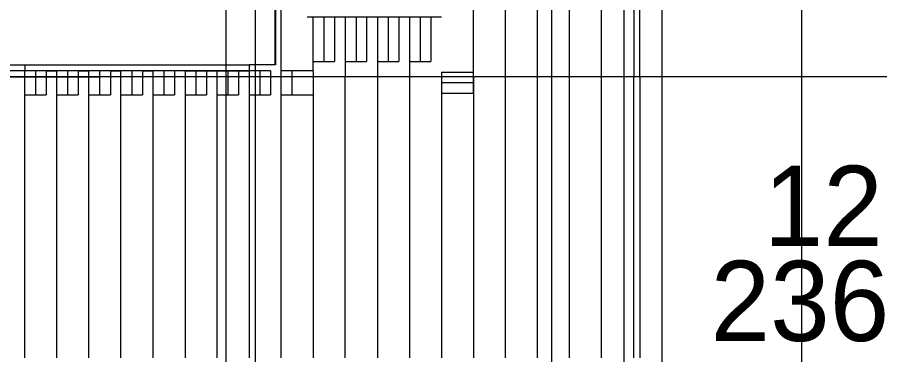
# Model space of a CAD drawing. Extents: x -264165 to -263575, y -1242333 to -1242036.
# Drawn here: x -263907.56 to -263886.03, y -1242216.81 to -1242208.39 of the extents above; entities that cross this region are included whole.
import ezdxf

# ---------------------------------------------------------------- set-up
doc = ezdxf.new("R2010")
doc.units = 0
for name, color, linetype in [('KFA_BODY_VYTYCOVAK', 7, 'Continuous'), ('KFA_HESCON_OSI_STAVBY', 7, 'Continuous'), ('KFA_SITUACIA_DRS_VYTYCOVAK_SEDA', 7, 'Continuous')]:
    doc.layers.add(name, color=color, linetype=linetype)

msp = doc.modelspace()

# ---------------------------------------------------------------- linework, layer by layer
at = {"layer": 'KFA_HESCON_OSI_STAVBY'}
for p, q in [((-263901.618, -1242080.447), (-263901.618, -1242248.737)), ((-263894.218, -1242080.447), (-263894.218, -1242248.737)), ((-263892.418, -1242080.447), (-263892.418, -1242248.737)), ((-263891.468, -1242080.447), (-263891.468, -1242248.737)), ((-263787.486, -1242209.882), (-263921.823, -1242209.882)), ((-263920.885, -1242209.882), (-263905.505, -1242209.882))]:
    msp.add_line(p, q, dxfattribs=at)
at = {"layer": 'KFA_SITUACIA_DRS_VYTYCOVAK_SEDA'}
for p, q in [((-263887.968, -1242220.382), (-263887.968, -1242108.382)), ((-263901.118, -1242209.582), (-263901.118, -1242203.032)), ((-263901.118, -1242209.582), (-263901.118, -1242203.032)), ((-263901.108, -1242203.032), (-263901.108, -1242209.582)), ((-263901.108, -1242203.032), (-263901.108, -1242209.582)), ((-263900.968, -1242209.582), (-263900.968, -1242203.032)), ((-263900.968, -1242209.582), (-263900.968, -1242203.032)), ((-263896.168, -1242209.882), (-263896.168, -1242202.882)), ((-263896.168, -1242209.882), (-263896.168, -1242202.882)), ((-263895.368, -1242209.882), (-263895.368, -1242202.882)), ((-263895.368, -1242209.882), (-263895.368, -1242202.882)), ((-263894.568, -1242209.882), (-263894.568, -1242202.882)), ((-263894.568, -1242209.882), (-263894.568, -1242202.882)), ((-263893.768, -1242209.882), (-263893.768, -1242202.882)), ((-263893.768, -1242209.882), (-263893.768, -1242202.882)), ((-263892.968, -1242209.882), (-263892.968, -1242202.882)), ((-263892.968, -1242209.882), (-263892.968, -1242202.882)), ((-263902.343, -1242224.282), (-263902.343, -1242203.332)), ((-263896.168, -1242209.761), (-263896.168, -1242206.932)), ((-263896.168, -1242209.761), (-263896.168, -1242206.932)), ((-263892.168, -1242207.032), (-263892.168, -1242209.882)), ((-263892.168, -1242207.032), (-263892.168, -1242209.882)), ((-263892.018, -1242209.882), (-263892.018, -1242207.032)), ((-263892.018, -1242209.882), (-263892.018, -1242207.032)), ((-263900.168, -1242208.395), (-263900.318, -1242208.395)), ((-263900.168, -1242208.395), (-263900.318, -1242208.395)), ((-263899.901, -1242208.395), (-263900.168, -1242208.395)), ((-263899.901, -1242208.395), (-263900.168, -1242208.395)), ((-263900.168, -1242209.732), (-263900.168, -1242208.395)), ((-263900.168, -1242209.732), (-263900.168, -1242208.395)), ((-263899.901, -1242208.395), (-263899.901, -1242209.495)), ((-263899.901, -1242208.395), (-263899.901, -1242209.495)), ((-263899.634, -1242208.395), (-263899.901, -1242208.395)), ((-263899.634, -1242208.395), (-263899.901, -1242208.395)), ((-263899.634, -1242208.395), (-263899.634, -1242209.495)), ((-263899.634, -1242208.395), (-263899.634, -1242209.495)), ((-263899.368, -1242208.395), (-263899.634, -1242208.395)), ((-263899.368, -1242208.395), (-263899.634, -1242208.395)), ((-263899.101, -1242208.395), (-263899.368, -1242208.395)), ((-263899.101, -1242208.395), (-263899.368, -1242208.395)), ((-263899.368, -1242208.395), (-263899.368, -1242209.882)), ((-263899.368, -1242208.395), (-263899.368, -1242209.882)), ((-263899.101, -1242208.395), (-263899.101, -1242209.495)), ((-263899.101, -1242208.395), (-263899.101, -1242209.495)), ((-263898.835, -1242208.395), (-263899.101, -1242208.395)), ((-263898.835, -1242208.395), (-263899.101, -1242208.395)), ((-263898.835, -1242208.395), (-263898.835, -1242209.495)), ((-263898.835, -1242208.395), (-263898.835, -1242209.495)), ((-263898.568, -1242208.395), (-263898.835, -1242208.395)), ((-263898.568, -1242208.395), (-263898.835, -1242208.395)), ((-263898.301, -1242208.395), (-263898.568, -1242208.395)), ((-263898.301, -1242208.395), (-263898.568, -1242208.395)), ((-263898.568, -1242208.395), (-263898.568, -1242209.882)), ((-263898.568, -1242208.395), (-263898.568, -1242209.882)), ((-263898.301, -1242208.395), (-263898.301, -1242209.495)), ((-263898.301, -1242208.395), (-263898.301, -1242209.495)), ((-263898.034, -1242208.395), (-263898.301, -1242208.395)), ((-263898.034, -1242208.395), (-263898.301, -1242208.395)), ((-263898.034, -1242208.395), (-263898.034, -1242209.495)), ((-263898.034, -1242208.395), (-263898.034, -1242209.495)), ((-263897.768, -1242208.395), (-263898.034, -1242208.395)), ((-263897.768, -1242208.395), (-263898.034, -1242208.395)), ((-263897.501, -1242208.395), (-263897.768, -1242208.395)), ((-263897.501, -1242208.395), (-263897.768, -1242208.395)), ((-263897.768, -1242208.395), (-263897.768, -1242209.882)), ((-263897.768, -1242208.395), (-263897.768, -1242209.882)), ((-263897.234, -1242208.395), (-263897.501, -1242208.395)), ((-263897.234, -1242208.395), (-263897.501, -1242208.395)), ((-263897.501, -1242208.395), (-263897.501, -1242209.495)), ((-263897.501, -1242208.395), (-263897.501, -1242209.495)), ((-263897.234, -1242208.395), (-263897.234, -1242209.495)), ((-263897.234, -1242208.395), (-263897.234, -1242209.495)), ((-263896.968, -1242208.395), (-263897.234, -1242208.395)), ((-263896.968, -1242208.395), (-263897.234, -1242208.395)), ((-263900.168, -1242209.495), (-263899.901, -1242209.495)), ((-263900.168, -1242209.495), (-263899.901, -1242209.495)), ((-263899.901, -1242209.495), (-263899.634, -1242209.495)), ((-263899.901, -1242209.495), (-263899.634, -1242209.495)), ((-263899.368, -1242209.495), (-263899.101, -1242209.495)), ((-263899.368, -1242209.495), (-263899.101, -1242209.495)), ((-263899.101, -1242209.495), (-263898.835, -1242209.495)), ((-263899.101, -1242209.495), (-263898.835, -1242209.495)), ((-263898.568, -1242209.495), (-263898.301, -1242209.495)), ((-263898.568, -1242209.495), (-263898.301, -1242209.495)), ((-263898.301, -1242209.495), (-263898.034, -1242209.495)), ((-263898.301, -1242209.495), (-263898.034, -1242209.495)), ((-263897.768, -1242209.495), (-263897.501, -1242209.495)), ((-263897.768, -1242209.495), (-263897.501, -1242209.495)), ((-263897.501, -1242209.495), (-263897.234, -1242209.495)), ((-263897.501, -1242209.495), (-263897.234, -1242209.495)), ((-263907.893, -1242209.582), (-263907.368, -1242209.582)), ((-263907.893, -1242209.582), (-263907.368, -1242209.582)), ((-263907.368, -1242209.582), (-263907.368, -1242209.732)), ((-263907.368, -1242209.582), (-263907.368, -1242209.732)), ((-263907.368, -1242209.582), (-263901.768, -1242209.582)), ((-263907.368, -1242209.582), (-263901.768, -1242209.582)), ((-263901.108, -1242209.582), (-263901.768, -1242209.582)), ((-263901.108, -1242209.582), (-263901.768, -1242209.582)), ((-263901.768, -1242209.582), (-263901.768, -1242209.732)), ((-263901.768, -1242209.582), (-263901.768, -1242209.732)), ((-263901.768, -1242209.582), (-263901.768, -1242209.732)), ((-263901.768, -1242209.582), (-263901.768, -1242209.732)), ((-263900.968, -1242216.882), (-263900.968, -1242209.582)), ((-263900.968, -1242216.882), (-263900.968, -1242209.582)), ((-263907.368, -1242209.732), (-263907.893, -1242209.732)), ((-263907.368, -1242209.732), (-263907.893, -1242209.732)), ((-263907.368, -1242209.732), (-263907.893, -1242209.732)), ((-263907.368, -1242209.732), (-263907.893, -1242209.732)), ((-263907.101, -1242209.732), (-263907.368, -1242209.732)), ((-263907.101, -1242209.732), (-263907.368, -1242209.732)), ((-263907.368, -1242216.882), (-263907.368, -1242209.732)), ((-263907.368, -1242216.882), (-263907.368, -1242209.732)), ((-263901.768, -1242209.732), (-263907.368, -1242209.732)), ((-263901.768, -1242209.732), (-263907.368, -1242209.732)), ((-263907.101, -1242209.732), (-263907.101, -1242210.332)), ((-263907.101, -1242209.732), (-263907.101, -1242210.332)), ((-263906.834, -1242209.732), (-263907.101, -1242209.732)), ((-263906.834, -1242209.732), (-263907.101, -1242209.732)), ((-263906.834, -1242209.732), (-263906.834, -1242210.332)), ((-263906.834, -1242209.732), (-263906.834, -1242210.332)), ((-263906.834, -1242209.732), (-263906.568, -1242209.732)), ((-263906.834, -1242209.732), (-263906.568, -1242209.732)), ((-263906.301, -1242209.732), (-263906.568, -1242209.732)), ((-263906.301, -1242209.732), (-263906.568, -1242209.732)), ((-263906.568, -1242216.882), (-263906.568, -1242209.732)), ((-263906.568, -1242216.882), (-263906.568, -1242209.732)), ((-263906.301, -1242209.732), (-263906.301, -1242210.332)), ((-263906.301, -1242209.732), (-263906.301, -1242210.332)), ((-263906.034, -1242209.732), (-263906.301, -1242209.732)), ((-263906.034, -1242209.732), (-263906.301, -1242209.732)), ((-263906.034, -1242209.732), (-263906.034, -1242210.332)), ((-263906.034, -1242209.732), (-263906.034, -1242210.332)), ((-263906.034, -1242209.732), (-263905.768, -1242209.732)), ((-263906.034, -1242209.732), (-263905.768, -1242209.732)), ((-263905.768, -1242209.732), (-263905.908, -1242209.732)), ((-263905.768, -1242209.732), (-263905.908, -1242209.732)), ((-263905.501, -1242209.732), (-263905.768, -1242209.732)), ((-263905.501, -1242209.732), (-263905.768, -1242209.732)), ((-263905.768, -1242216.882), (-263905.768, -1242209.732)), ((-263905.768, -1242216.882), (-263905.768, -1242209.732)), ((-263905.501, -1242209.732), (-263905.501, -1242210.332)), ((-263905.501, -1242209.732), (-263905.501, -1242210.332)), ((-263905.234, -1242209.732), (-263905.501, -1242209.732)), ((-263905.234, -1242209.732), (-263905.501, -1242209.732)), ((-263905.234, -1242209.732), (-263905.234, -1242210.332)), ((-263905.234, -1242209.732), (-263905.234, -1242210.332)), ((-263905.234, -1242209.732), (-263904.968, -1242209.732)), ((-263905.234, -1242209.732), (-263904.968, -1242209.732)), ((-263904.968, -1242209.732), (-263905.108, -1242209.732)), ((-263904.968, -1242209.732), (-263905.108, -1242209.732)), ((-263904.701, -1242209.732), (-263904.968, -1242209.732)), ((-263904.701, -1242209.732), (-263904.968, -1242209.732)), ((-263904.968, -1242216.882), (-263904.968, -1242209.732)), ((-263904.968, -1242216.882), (-263904.968, -1242209.732)), ((-263904.701, -1242209.732), (-263904.701, -1242210.332)), ((-263904.701, -1242209.732), (-263904.701, -1242210.332)), ((-263904.434, -1242209.732), (-263904.701, -1242209.732)), ((-263904.434, -1242209.732), (-263904.701, -1242209.732)), ((-263904.434, -1242209.732), (-263904.434, -1242210.332)), ((-263904.434, -1242209.732), (-263904.434, -1242210.332)), ((-263904.434, -1242209.732), (-263904.168, -1242209.732)), ((-263904.434, -1242209.732), (-263904.168, -1242209.732)), ((-263904.168, -1242209.732), (-263904.308, -1242209.732)), ((-263904.168, -1242209.732), (-263904.308, -1242209.732)), ((-263903.901, -1242209.732), (-263904.168, -1242209.732)), ((-263903.901, -1242209.732), (-263904.168, -1242209.732)), ((-263903.368, -1242209.732), (-263904.168, -1242209.732)), ((-263903.368, -1242209.732), (-263904.168, -1242209.732)), ((-263904.168, -1242216.882), (-263904.168, -1242209.732)), ((-263904.168, -1242216.882), (-263904.168, -1242209.732)), ((-263903.901, -1242209.732), (-263903.901, -1242210.332)), ((-263903.901, -1242209.732), (-263903.901, -1242210.332)), ((-263903.634, -1242209.732), (-263903.901, -1242209.732)), ((-263903.634, -1242209.732), (-263903.901, -1242209.732)), ((-263903.634, -1242209.732), (-263903.634, -1242210.332)), ((-263903.634, -1242209.732), (-263903.634, -1242210.332)), ((-263903.101, -1242209.732), (-263903.368, -1242209.732)), ((-263903.101, -1242209.732), (-263903.368, -1242209.732)), ((-263903.368, -1242209.732), (-263902.568, -1242209.732)), ((-263903.368, -1242209.732), (-263902.568, -1242209.732)), ((-263903.368, -1242209.732), (-263903.368, -1242216.882)), ((-263903.368, -1242209.732), (-263903.368, -1242216.882)), ((-263903.101, -1242209.732), (-263903.101, -1242210.332)), ((-263903.101, -1242209.732), (-263903.101, -1242210.332)), ((-263902.834, -1242209.732), (-263903.101, -1242209.732)), ((-263902.834, -1242209.732), (-263903.101, -1242209.732)), ((-263902.834, -1242209.732), (-263902.834, -1242210.332)), ((-263902.834, -1242209.732), (-263902.834, -1242210.332)), ((-263902.301, -1242209.732), (-263902.568, -1242209.732)), ((-263902.301, -1242209.732), (-263902.568, -1242209.732)), ((-263902.568, -1242209.732), (-263901.768, -1242209.732)), ((-263902.568, -1242209.732), (-263901.768, -1242209.732)), ((-263902.568, -1242216.882), (-263902.568, -1242209.732)), ((-263902.568, -1242216.882), (-263902.568, -1242209.732)), ((-263902.301, -1242209.732), (-263902.301, -1242210.332)), ((-263902.301, -1242209.732), (-263902.301, -1242210.332)), ((-263902.034, -1242209.732), (-263902.301, -1242209.732)), ((-263902.034, -1242209.732), (-263902.301, -1242209.732)), ((-263902.034, -1242209.732), (-263902.034, -1242210.332)), ((-263902.034, -1242209.732), (-263902.034, -1242210.332)), ((-263901.501, -1242209.732), (-263901.768, -1242209.732)), ((-263901.501, -1242209.732), (-263901.768, -1242209.732)), ((-263901.768, -1242209.732), (-263901.768, -1242216.882)), ((-263901.768, -1242209.732), (-263901.768, -1242216.882)), ((-263901.768, -1242209.732), (-263901.768, -1242209.732)), ((-263901.768, -1242209.732), (-263901.768, -1242209.732)), ((-263901.501, -1242209.732), (-263901.501, -1242210.332)), ((-263901.501, -1242209.732), (-263901.501, -1242210.332)), ((-263901.234, -1242209.732), (-263901.501, -1242209.732)), ((-263901.234, -1242209.732), (-263901.501, -1242209.732)), ((-263901.234, -1242209.732), (-263901.234, -1242210.332)), ((-263901.234, -1242209.732), (-263901.234, -1242210.332)), ((-263900.701, -1242209.732), (-263900.968, -1242209.732)), ((-263900.701, -1242209.732), (-263900.968, -1242209.732)), ((-263900.701, -1242209.732), (-263900.701, -1242210.332)), ((-263900.701, -1242209.732), (-263900.701, -1242210.332)), ((-263900.168, -1242209.732), (-263900.701, -1242209.732)), ((-263900.168, -1242209.732), (-263900.701, -1242209.732)), ((-263900.168, -1242209.732), (-263900.168, -1242210.332)), ((-263900.168, -1242209.732), (-263900.168, -1242210.332)), ((-263899.368, -1242216.882), (-263899.368, -1242209.882)), ((-263899.368, -1242216.882), (-263899.368, -1242209.882)), ((-263898.568, -1242209.882), (-263898.568, -1242216.882)), ((-263898.568, -1242209.882), (-263898.568, -1242216.882)), ((-263897.768, -1242209.882), (-263897.768, -1242216.882)), ((-263897.768, -1242209.882), (-263897.768, -1242216.882)), ((-263896.968, -1242209.761), (-263896.168, -1242209.761)), ((-263896.968, -1242209.761), (-263896.168, -1242209.761)), ((-263896.968, -1242209.761), (-263896.968, -1242209.882)), ((-263896.968, -1242209.761), (-263896.968, -1242209.882)), ((-263896.968, -1242209.882), (-263896.968, -1242216.882)), ((-263896.968, -1242209.882), (-263896.968, -1242216.882)), ((-263896.168, -1242210.028), (-263896.168, -1242209.761)), ((-263896.168, -1242210.028), (-263896.168, -1242209.761)), ((-263896.168, -1242209.882), (-263896.168, -1242216.882)), ((-263896.168, -1242209.882), (-263896.168, -1242216.882)), ((-263895.368, -1242216.882), (-263895.368, -1242209.882)), ((-263895.368, -1242216.882), (-263895.368, -1242209.882)), ((-263894.568, -1242216.882), (-263894.568, -1242209.882)), ((-263894.568, -1242216.882), (-263894.568, -1242209.882)), ((-263893.768, -1242216.882), (-263893.768, -1242209.882)), ((-263893.768, -1242216.882), (-263893.768, -1242209.882)), ((-263892.968, -1242216.882), (-263892.968, -1242209.882)), ((-263892.968, -1242216.882), (-263892.968, -1242209.882)), ((-263892.168, -1242216.882), (-263892.168, -1242209.882)), ((-263892.168, -1242216.882), (-263892.168, -1242209.882)), ((-263892.018, -1242209.882), (-263892.018, -1242216.882)), ((-263892.018, -1242209.882), (-263892.018, -1242216.882)), ((-263896.168, -1242210.028), (-263896.968, -1242210.028)), ((-263896.168, -1242210.028), (-263896.968, -1242210.028)), ((-263896.168, -1242210.295), (-263896.168, -1242210.028)), ((-263896.168, -1242210.295), (-263896.168, -1242210.028)), ((-263907.368, -1242210.332), (-263907.101, -1242210.332)), ((-263907.368, -1242210.332), (-263907.101, -1242210.332)), ((-263907.101, -1242210.332), (-263906.834, -1242210.332)), ((-263907.101, -1242210.332), (-263906.834, -1242210.332)), ((-263906.568, -1242210.332), (-263906.301, -1242210.332)), ((-263906.568, -1242210.332), (-263906.301, -1242210.332)), ((-263906.301, -1242210.332), (-263906.034, -1242210.332)), ((-263906.301, -1242210.332), (-263906.034, -1242210.332)), ((-263905.768, -1242210.332), (-263905.501, -1242210.332)), ((-263905.768, -1242210.332), (-263905.501, -1242210.332)), ((-263905.501, -1242210.332), (-263905.234, -1242210.332)), ((-263905.501, -1242210.332), (-263905.234, -1242210.332)), ((-263904.968, -1242210.332), (-263904.701, -1242210.332)), ((-263904.968, -1242210.332), (-263904.701, -1242210.332)), ((-263904.701, -1242210.332), (-263904.434, -1242210.332)), ((-263904.701, -1242210.332), (-263904.434, -1242210.332)), ((-263904.168, -1242210.332), (-263903.901, -1242210.332)), ((-263904.168, -1242210.332), (-263903.901, -1242210.332)), ((-263903.901, -1242210.332), (-263903.634, -1242210.332)), ((-263903.901, -1242210.332), (-263903.634, -1242210.332)), ((-263903.368, -1242210.332), (-263903.101, -1242210.332)), ((-263903.368, -1242210.332), (-263903.101, -1242210.332)), ((-263903.101, -1242210.332), (-263902.834, -1242210.332)), ((-263903.101, -1242210.332), (-263902.834, -1242210.332)), ((-263902.568, -1242210.332), (-263902.301, -1242210.332)), ((-263902.568, -1242210.332), (-263902.301, -1242210.332)), ((-263902.301, -1242210.332), (-263902.034, -1242210.332)), ((-263902.301, -1242210.332), (-263902.034, -1242210.332)), ((-263901.768, -1242210.332), (-263901.501, -1242210.332)), ((-263901.768, -1242210.332), (-263901.501, -1242210.332)), ((-263901.501, -1242210.332), (-263901.234, -1242210.332)), ((-263901.501, -1242210.332), (-263901.234, -1242210.332)), ((-263900.968, -1242210.332), (-263900.701, -1242210.332)), ((-263900.968, -1242210.332), (-263900.701, -1242210.332)), ((-263900.701, -1242210.332), (-263900.168, -1242210.332)), ((-263900.701, -1242210.332), (-263900.168, -1242210.332)), ((-263900.168, -1242210.332), (-263900.168, -1242216.882)), ((-263900.168, -1242210.332), (-263900.168, -1242216.882)), ((-263896.168, -1242210.295), (-263896.968, -1242210.295)), ((-263896.168, -1242210.295), (-263896.968, -1242210.295))]:
    msp.add_line(p, q, dxfattribs=at)

# ---------------------------------------------------------------- texts
at = {"layer": 'KFA_BODY_VYTYCOVAK'}
for s, p in [('12', (-263888.923, -1242214.096)), ('236.16', (-263890.25, -1242216.466))]:
    msp.add_text(s, height=2, dxfattribs=at).set_placement(p)

doc.saveas('drawing.dxf')
